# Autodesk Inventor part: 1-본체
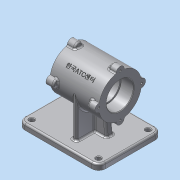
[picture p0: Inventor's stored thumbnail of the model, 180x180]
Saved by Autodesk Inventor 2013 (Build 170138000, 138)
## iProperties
Created: 2015-12
Part Number: 1-본체
Material: 알루미늄 6061
Document SubType Name: Modeling
Designer: dgall
Density: 2.71 g/cm^3
Mass: 1164.14 g
Surface Area: 815.882 cm^2
Volume: 429.573 cm^3
Author: dgall
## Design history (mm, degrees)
sketch "스케치1"
  geometry: L1 (-42.5, 0)-(42.5, 0); L2 (-42.5, 0)-(-42.5, 37); L3 (-42.5, 37)-(42.5, 37); L4 (42.5, 37)-(42.5, 0); L5 (-42.5, 23.5)-(-20.5, 23.5); L6 (-20.5, 23.5)-(-20.5, 21); L7 (-20.5, 21)-(20.5, 21); L8 (20.5, 21)-(20.5, 23.5); L9 (20.5, 23.5)-(42.5, 23.5); 2 further points
  constraints: 18 end point, 5 perpendicular, 3 parallel, 2 coincident, 2 point on line, 1 horizontal, 1 midpoint
  dimensions: "d0" = 85 distance of L1.start L1.end; "d1" = 74 diameter of L3 L1; "d2" = 47 diameter of L5 L1; "d3" = 47 diameter of L9 L1; "d4" = 42 diameter of L7 L1; "d5" = 22 distance of L5.start L5.end; "d6" = 22 distance of L8.end L9.end
revolve "회전1" sketch "스케치1" stored, may be unused: angle "d7" = 90 deg
sketch "스케치2"
  geometry: L1 (-80, -80)-(60, -80); L2 (-42.5, -37)-(-42.5, 37) reference; L3 (-80, -70)-(60, -70); L4 (-80, -70)-(-80, -80); L5 (60, -70)-(60, -80); 1 further point
  constraints: 8 end point, 2 parallel, 1 horizontal, 1 perpendicular
  dimensions: "d8" = 80 distance from line of L1 point (0, 0); "d9" = 140 distance of L1.start L1.end; "d10" = 37.5 distance from line of L1.start L2; "d11" = 10 distance between parallel lines of L3 L1
extrude "돌출1" join sketch "스케치2" stored distance "d12" = 110; taper "d13" = 0 deg
sketch "스케치3"
  geometry: L1 (0, 110)-(0, 0) reference; L2 (0, 110)-(140, 110) reference; L3 (76, 92)-(84, 92); L4 (84, 92)-(84, 18); L5 (84, 18)-(76, 18); L6 (76, 18)-(76, 92); L7 (55, 61)-(105, 61); L8 (105, 61)-(105, 49); L9 (105, 49)-(55, 49); L10 (55, 49)-(55, 61); 5 further points
  constraints: 16 end point, 4 midpoint, 4 parallel, 2 horizontal, 2 horizontal alignment, 2 perpendicular, 2 vertical alignment
  dimensions: "d14" = 76 distance between parallel lines of L6 L1; "d15" = 12 distance between parallel lines of L9 L7; "d16" = 50 distance of L8.end L9.end; "d17" = 74 distance of L3.end L4.end; "d18" = 8 distance between parallel lines of L4 L6 (derived); "d19" = 49 distance between parallel lines of L7 L2 (derived)
extrude "돌출2" join sketch "스케치3" stored distance "d20" = 110; taper "d21" = 0 deg
extrude "돌출3" join sketch "스케치3" stored distance "d22" = 110; taper "d23" = 0 deg
feature "면 기울기1" dims angle "d24" = 7 deg
feature "면 기울기2" dims angle "d25" = 7 deg
fillet "모깎기1" dims "d30" = 12
hole "구멍1" diameter "d33" = 8; stored, may be unused: countersink angle "d37" = 90 deg, drill point angle "d39" = 118 deg; dims "d31" = 10, "d32" = 10, "d34" = 6, "d35" = 10, "d36" = 2, "d38" = 8
fillet "모깎기2" dims "d46" = 0.3
chamfer "모따기1" distance "d47" = 1; stored, may be unused: second distance "d48" = 2, angle "d49" = 45 deg
fillet "모깎기3" dims "d50" = 3
fillet "모깎기4" dims "d51" = 3
node "작업 평면2"
  node "작업 평면1"
sketch "스케치8"
  geometry: L1 (42.5, -26.163)-(42.5, -26.163) reference; 2 further points
  constraints: 1 coincident, 1 other
  dimensions: "d68" = 42.5 distance from line of point (0, 0) L1 (derived)
feature "엠보싱1" sketch "스케치8" dims "d0" = 85, "d1" = 74, "d2" = 47, "d3" = 47, "d4" = 42, "d5" = 22, "d6" = 22, "d69" = 0.5, "d70" = 0
sketch "스케치9"
  geometry: L1 (-42.5, -37)-(-42.5, 37) reference; L2 (-42.5, 37)-(42.5, 37) reference; L3 (-42.5, 37)-(-27.5, 37); L4 (-42.5, 37)-(-42.5, 44); L5 (-42.5, 44)-(-30.048, 44); L6 (-30.048, 44)-(-27.5, 37); 1 further point
  constraints: 8 end point, 2 perpendicular, 1 point on line
  dimensions: "d71" = 15 distance of L2.start L3.end; "d72" = 7 distance of L2.start L4.end; "d73" = 110 deg angle of L2 L6
revolve "회전2" sketch "스케치9" stored, may be unused: angle "d74" = 90 deg
fillet "모깎기5" dims "d75" = 3
fillet "모깎기6" dims "d76" = 3
hole "구멍3" diameter "d79" = 3.459; stored, may be unused: countersink angle "d83" = 90 deg, drill point angle "d85" = 118 deg; dims "d77" = 10, "d78" = 10, "d80" = 9, "d81" = 10, "d82" = 2, "d84" = 11
node "솔리드1"
pattern_linear "직사각형 패턴1" dims "d42" = 86, "d45" = 116
pattern_circular "원형 패턴3" dims "d87" = 360 deg
mirror "대칭2"
node "작업축1"
other parameters: "d67" = -45 deg
